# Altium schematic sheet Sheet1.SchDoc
size C; SheetNumber: 1; SheetTotal: 1
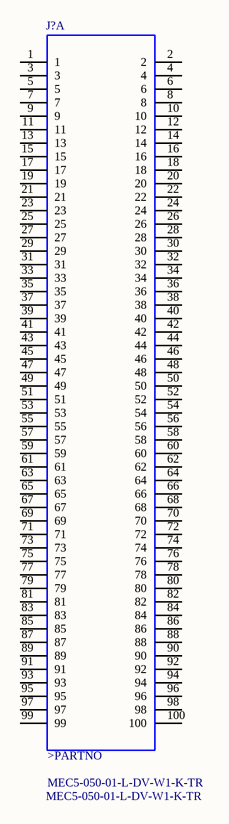
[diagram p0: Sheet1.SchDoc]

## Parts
J?  MEC5-050-01-L-DV-W1-K-TR  [MEC5-050-01-L-DV-W1-K-TR]  (part A of 2)

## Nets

Not connected (* = marked no-connect by the designer): J? 1 2 3 4 5 6 7 8 9 10 11 12 13 14 15 16 17 18 19 20 21 22 23 24 25 26 27 28 29 30 31 32 33 34 35 36 37 38 39 40 41 42 43 44 45 46 47 48 49 50 51 52 53 54 55 56 57 58 59 60 61 62 63 64 65 66 67 68 69 70 71 72 73 74 75 76 77 78 79 80 81 82 83 84 85 86 87 88 89 90 91 92 93 94 95 96 97 98 99 100

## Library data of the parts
J? = MEC5-050-01-L-DV-W1-K-TR: MF: Samtec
